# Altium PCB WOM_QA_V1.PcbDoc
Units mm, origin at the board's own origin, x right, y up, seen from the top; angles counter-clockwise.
Board outline 20 x 63 mm, 4 copper layers (Top Layer, Int1 (GND), Int2 (PWR), Bottom Layer), stack 1.426 mm thick; 29 components, 19 nets, 107 pads, 35 vias.
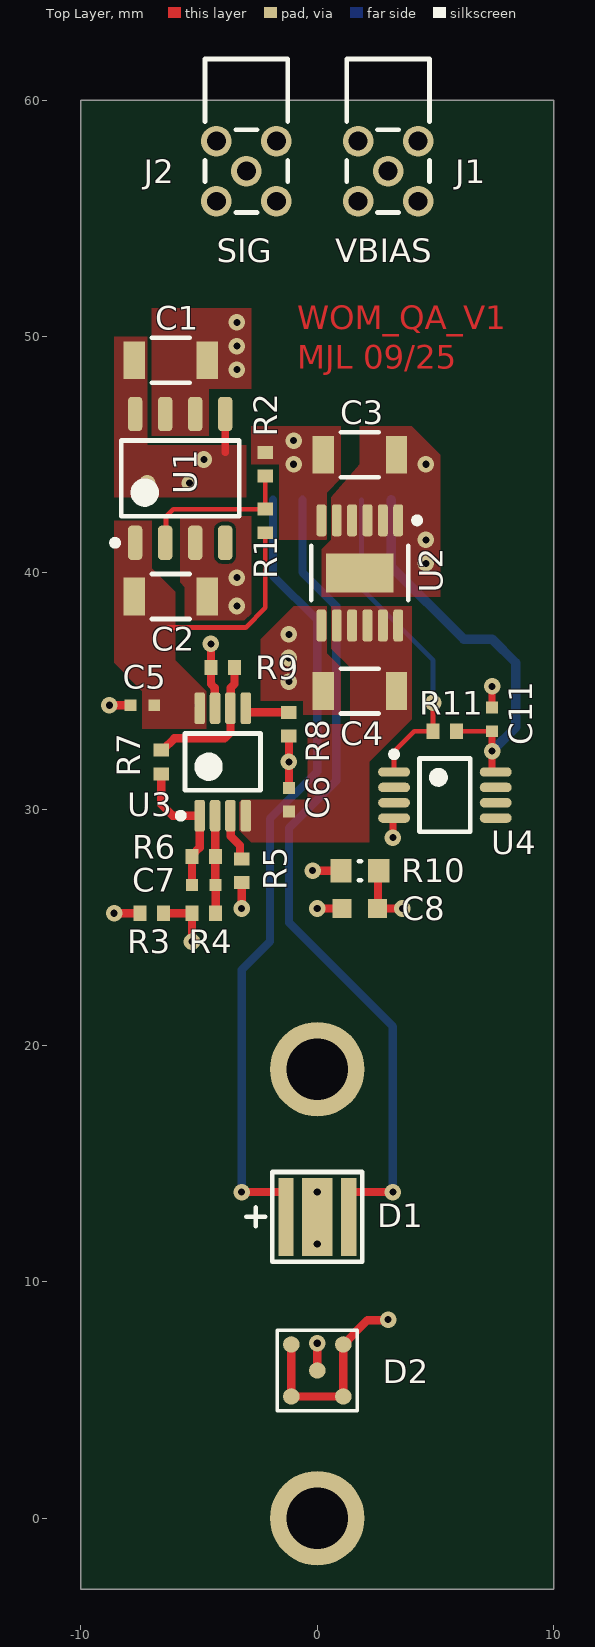
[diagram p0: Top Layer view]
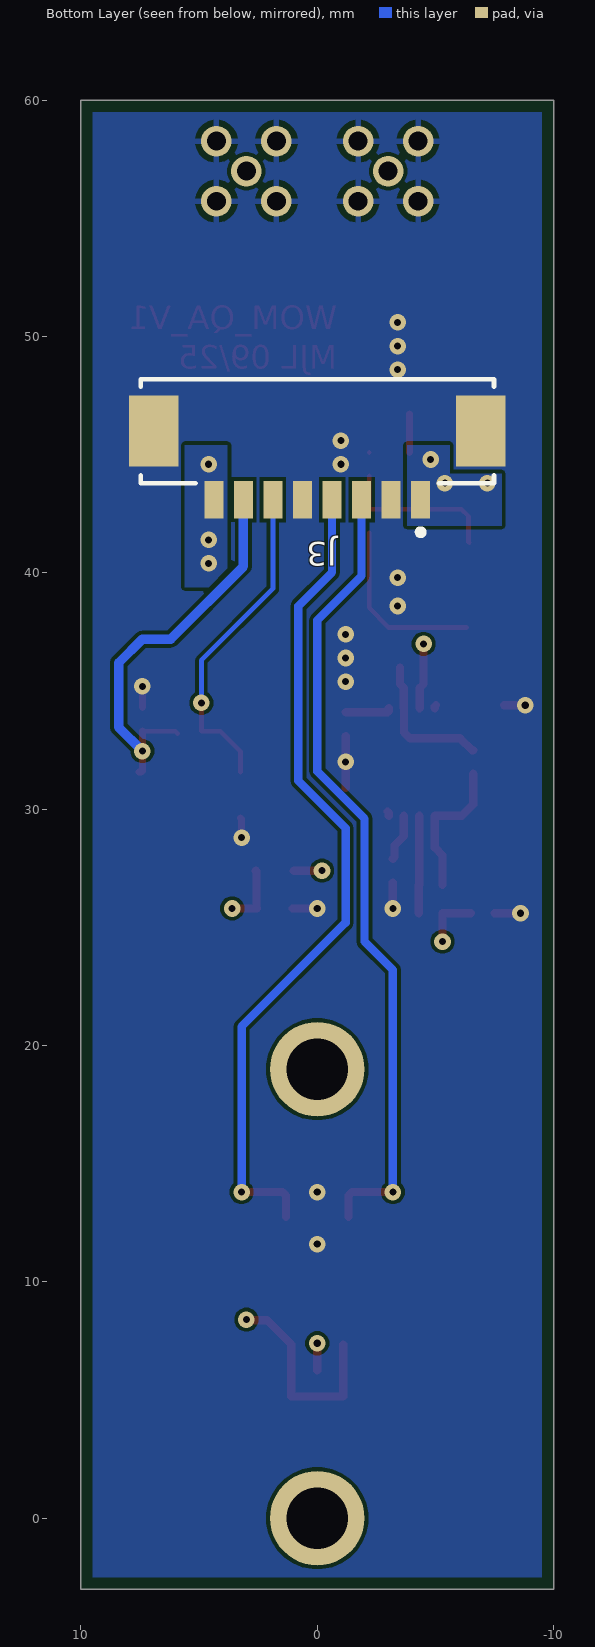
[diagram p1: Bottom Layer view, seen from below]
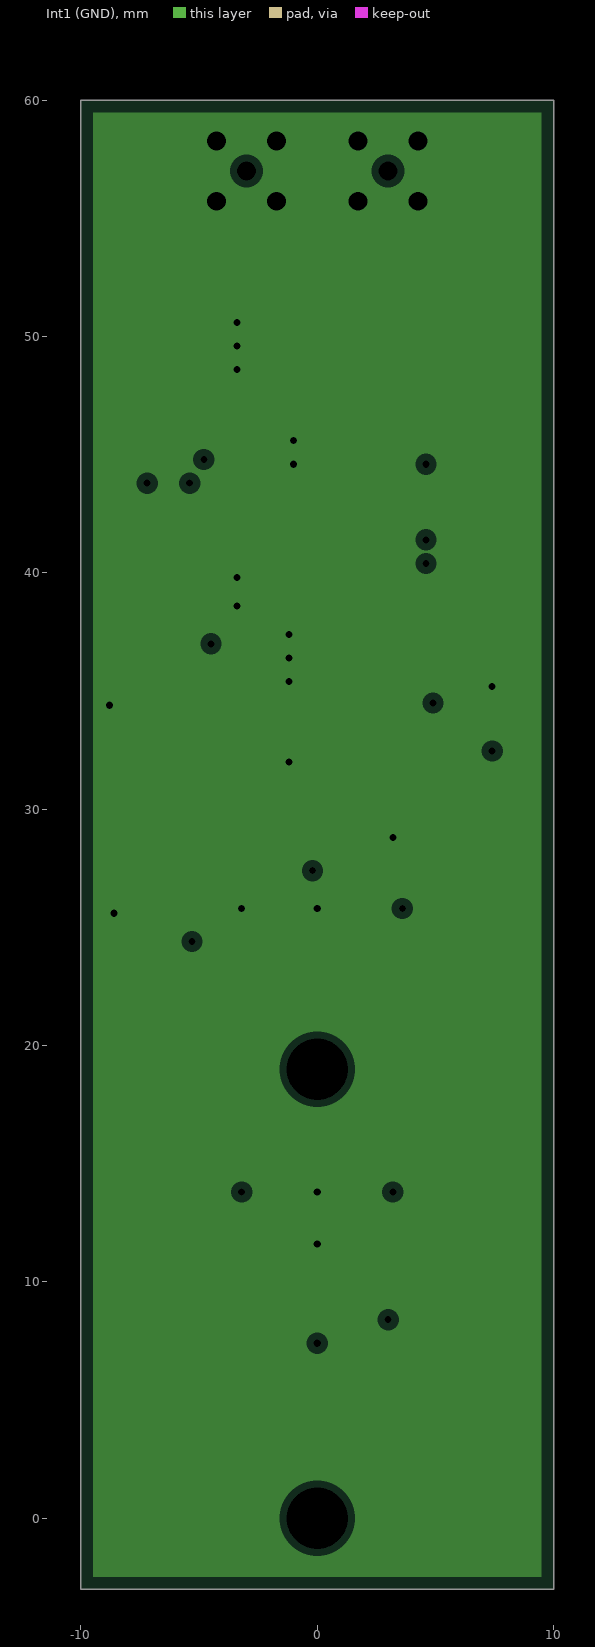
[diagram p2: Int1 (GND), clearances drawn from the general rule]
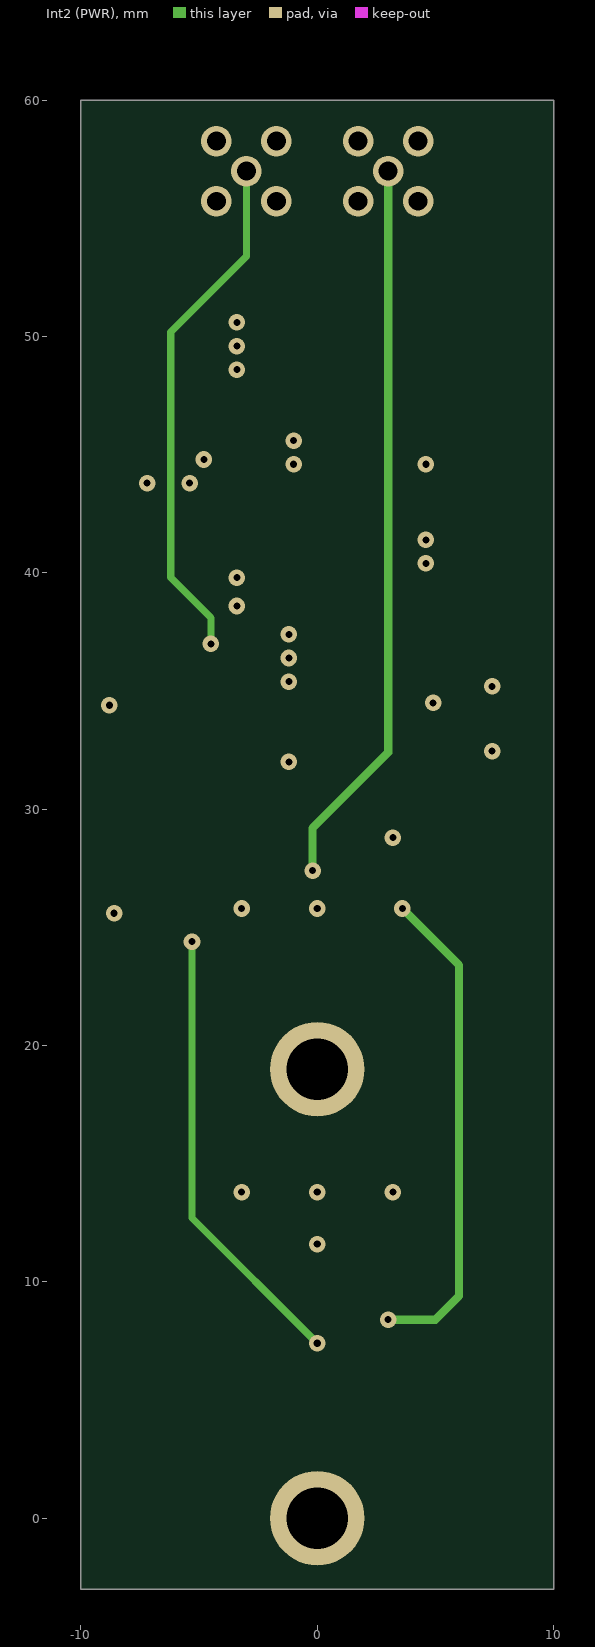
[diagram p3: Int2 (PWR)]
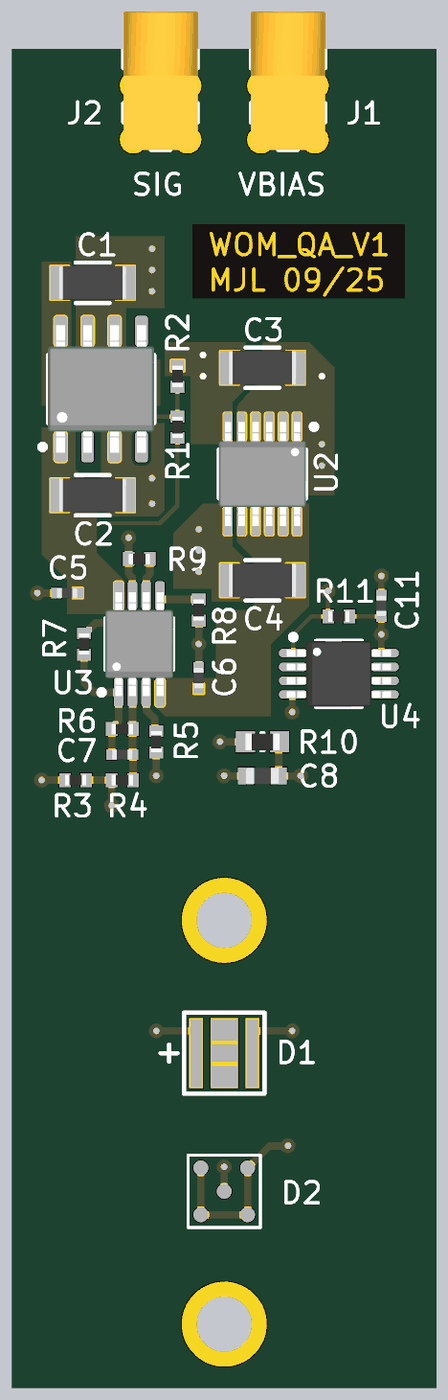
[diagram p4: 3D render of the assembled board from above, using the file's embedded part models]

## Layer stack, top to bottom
Top Solder: solder mask 0.015, SM-001, Dk 3.5
Top Layer: signal copper 0.035
Dielectric 1: prepreg 0.288, PP-017, Dk 4.5
Int1 (GND): plane copper 0.035, net GND
Dielectric 3: core 0.71, Core-039, Dk 4.7
Int2 (PWR): signal copper 0.035
Dielectric 5: prepreg 0.288, PP-017, Dk 4.5
Bottom Layer: signal copper 0.035
Bottom Solder: solder mask 0.015, SM-001, Dk 3.5

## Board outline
-10,-3 10,-3 10,60 -10,60

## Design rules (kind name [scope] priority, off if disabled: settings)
Clearance [All] p1: gap=0.15 ignorepadtopadclearanceinfootprint=FALSE
PlaneClearance [All] p1: clearance=0.3
PlaneConnect [All] p1: pad.planeconnectstyle=Relief pad.reliefexpansion=0.3 pad.reliefentries=4 pad.reliefconductorwidth=0.25 pad.reliefairgap=0.25 via.planeconnectstyle=Direct via.reliefexpansion=0.3 via.reliefentries=4 via.reliefconductorwidth=0.25 via.reliefairgap=0.25
PolygonConnect [All] p1: thpad.connectstyle=Relief thpad.reliefconductorwidth=0.25 thpad.reliefentries=4 thpad.polygonreliefangle="90 Angle" thpad.airgapwidth=0.25 smdpad.connectstyle=Direct smdpad.reliefconductorwidth=0.254 smdpad.reliefentries=4 smdpad.polygonreliefangle="90 Angle" smdpad.airgapwidth=0.254 via.connectstyle=Direct via.reliefconductorwidth=0.254 via.reliefentries=4 via.polygonreliefangle="90 Angle" via.airgapwidth=0.254
RoutingVias [All] p1: holewidth=0.3 width=0.7 viastyle="Through Hole" minholewidth=0.15 minwidth=0.45 maxholewidth=0.711 maxwidth=1.27
SilkToSilkClearance [All] p1: silktosilkclearance=0.15
SolderMaskExpansion SolderMaskExpansion_1 [IsVia] p1: expansion=0.102 istentingtop=TRUE
SolderMaskExpansion [All] p2: expansion=0.05 istentingtop=FALSE
SupplyNets "Schematic Supply Nets_6" [InNet('VDD_TEMP')] p1: voltage=0.000
SupplyNets "Schematic Supply Nets_4" [InNet('-7V0')] p2: voltage=0.000
SupplyNets "Schematic Supply Nets_3" [InNet('-5V0')] p3: voltage=0.000
SupplyNets "Schematic Supply Nets_2" [InNet('GND')] p4: voltage=0.000
SupplyNets "Schematic Supply Nets_1" [InNet('+7V0')] p5: voltage=0.000
SupplyNets "Schematic Supply Nets" [InNet('+5V0')] p6: voltage=0.000
Width Width_S50 [InNetClass('S50')] p1: maxlimit=0.496 minlimit=0.3 preferedwidth=0.496 toplayer_minwidth=0.35 toplayer_maxwidth=0.35 toplayer_prefwidth=0.35 midlayer2_maxwidth=0.3 midlayer2_prefwidth=0.3 bottomlayer_minwidth=0.496 impedanceprofiledriven=TRUE impedanceprofileid={FA672DF7-ECF2-4436-9E1C-940F573E7293} impedanceprofilevalue=50.000000 minimp=50.000000 maximp=50.000000 favimp=50.000000
Width [All] p2: maxlimit=4 minlimit=0.15 preferedwidth=0.25
27 further rules are at their usual default settings.

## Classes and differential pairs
net class S50: NetC7_1 NetC7_2 NetD2_1 NetR7_2 SIG_OUT

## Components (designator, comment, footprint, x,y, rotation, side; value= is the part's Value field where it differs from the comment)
C1 "10uF 16V" WCAP-CSGP_1206_H=1.6mm -6.2,49 r180 top value=10µF
C2 "10uF 16V" WCAP-CSGP_1206_H=1.6mm -6.2,39 r180 top value=10µF
C3 "10uF 16V" WCAP-CSGP_1206_H=1.6mm 1.8,45 r0 top value=10µF
C4 "10uF 16V" WCAP-CSGP_1206_H=1.6mm 1.8,35 r0 top value=10µF
C5 "100nF, 16V" WCAP-CSGP_0402_H=0.5mm -7.4,34.4 r0 top value=100nF
C6 "100nF, 16V" WCAP-CSGP_0402_H=0.5mm -1.2,30.4 r270 top value=100nF
C7 "20 pF 1%, 10V, NP0" WCAP-CSGP_0402_H=0.5mm -4.8,26.8 r180 top value=10pF
C8 "100nF 100V" WCAP-CSGP_0603_H=0.8mm_Reflow 1.8,25.8 r0 top value=100nF
C11 "100nF, 16V" WCAP-CSGP_0402_H=0.5mm 7.4,33.8 r270 top value=100nF
D1 "AUV3-ST32-0SV0K" AUV3-ST32-0SV0K-Footprint-1 0,12.75 r0 top locked
D2 "S13360-3050VE" S13360-3050VE-Footprint-1 0,6.25 r0 top locked
J1 "66011002111501" 66011002111501 3,57 r180 top
J2 "66011002111501" 66011002111501 -3,57 r180 top
J3 "53261-0871" FP-532610871-MFG 0,46 r180 bottom
R1 "3k16 0.1%" RESC0402(1005)_N -2.2,42.2 r270 top
R2 "1k 0.1%" RESC0402(1005)_N -2.2,44.6 r270 top
R3 "DNP" RESC0402(1005)_N -7,25.6 r0 top
R4 "51R 0.5%" RESC0402(1005)_N -4.8,25.6 r180 top
R5 "10R 0.5%" RESC0402(1005)_N -3.2,27.4 r90 top
R6 "2k2 0.5%" RESC0402(1005)_N -4.8,28 r180 top
R7 "510R 0.5%" RESC0402(1005)_N -6.6,32 r90 top
R8 "430R 0.5%" RESC0402(1005)_N -1.2,33.6 r90 top
R9 "2k2 0.5%" RESC0402(1005)_N -4,36 r180 top
R10 "1k 0.5%" RESC0603(1608)_N 1.8,27.4 r180 top
R11 "4k7 1%" RESC0402(1005)_N 5.4,33.3 r0 top
U1 "LT1963AES8#TRPBF" SOIC127P600X175-8N -5.8,44 r90 top
U2 "LT3015EMSE-5#PBF" TSOP65P490X110_HS-13N 1.8,40 r270 top
U3 "ADA4896-2ARMZ" TSOP65P490X110-8N -4,32 r90 top
U4 "DS18B20U+" MAXM-U8+1_V 5.4,30.6 r0 top

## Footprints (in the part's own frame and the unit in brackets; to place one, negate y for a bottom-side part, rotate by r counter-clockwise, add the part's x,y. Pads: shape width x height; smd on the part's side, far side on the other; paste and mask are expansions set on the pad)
66011002111501 [mm] "MMCX PCB THT Jack"
  round 1.3 hole 0.8: 1(0,0) 2(-1.27,1.27) 3(1.27,1.27) 4(1.27,-1.27) 5(-1.27,-1.27)
  silkscreen extent -1.75,-4.75 1.75,1.75, body extent -1.75,-4.75 1.75,1.75, height 3.8
AUV3-ST32-0SV0K-Footprint-1 [mm]
  rect 0.65x3.3 smd paste-0.05 mask+0.05: A(-1.325,0) C(1.325,0)
  rect 1.3x3.3 smd paste-4 mask+0.05: PAD(0,0)
  silkscreen extent -3,-1.9 1.9,1.9, body extent -1.75,-1.75 1.75,1.75, height 3.05
FP-532610871-MFG [mm]
  rect 0.8x1.6 smd paste+0 mask+0: 1(4.375,-2.9) 2(3.125,-2.9) 3(1.875,-2.9) 4(0.625,-2.9) 5(-0.625,-2.9) 6(-1.875,-2.9) 7(-3.125,-2.9) 8(-4.375,-2.9)
  rect 2.1x3 smd paste+0 mask+0: 9(-6.925,0) 10(6.925,0)
  silkscreen extent -7.47,-4.4 7.47,2.2, body extent -7.57,-3.1 7.57,2.1, height 3.6
MAXM-U8+1_V [mm] "SOP, 8-Leads, Body 3.1x3.1mm, Pitch 0.65mm"
  oval 1.35x0.4 smd: 1(-2.15,0.975) 2(-2.15,0.325) 3(-2.15,-0.325) 4(-2.15,-0.975) 5(2.15,-0.975) 6(2.15,-0.325) 7(2.15,0.325) 8(2.15,0.975)
  silkscreen extent -2.27,-1.55 1.07,1.85, body extent -2.45,-1.55 2.45,1.55, height 1.1
RESC0402(1005)_N [mm] "Chip Resistor, Body 1.0x0.5mm, IPC Medium Density"
  rect 0.55x0.65 smd: 1(-0.5,0) 2(0.5,0)
  body extent -0.5,-0.25 0.5,0.25, height 0.3
RESC0603(1608)_N [mm] "Chip Resistor, Body 1.6x0.8mm, IPC Medium Density"
  rect 0.9x1 smd: 1(-0.8,0) 2(0.8,0)
  silkscreen extent -0.05,-0.4 0.05,0.4, body extent -0.8,-0.4 0.8,0.4, height 0.4
S13360-3050VE-Footprint-1 [mm]
  round 0.7 smd mask+0.05: 1(0,0) 2(-1.1,-1.1) 2(-1.1,1.1) 2(1.1,-1.1) 2(1.1,1.1)
  silkscreen extent -1.7,-1.7 1.7,1.7, body extent -1.7,-1.7 1.7,1.7, height 1.4
SOIC127P600X175-8N [mm] "SOIC, 8-Leads, Body 4.90x3.91mm, Pitch 1.27mm, IPC Medium Density"
  rrect50% 1.45x0.6 smd: 1(-2.725,1.905) 2(-2.725,0.635) 3(-2.725,-0.635) 4(-2.725,-1.905) 5(2.725,-1.905) 6(2.725,-0.635) 7(2.725,0.635) 8(2.725,1.905)
  silkscreen extent -2.85,-2.5 1.6,2.88, body extent -3,-2.5 3,2.5, height 1.75
TSOP65P490X110-8N [mm] "TSOP, 8-Leads, Body 3.00x3.00mm, Pitch 0.65mm, IPC Medium Density"
  rrect50% 1.35x0.45 smd mask+0.05: 1(-2.275,0.975) 2(-2.275,0.325) 3(-2.275,-0.325) 4(-2.275,-0.975) 5(2.275,-0.975) 6(2.275,-0.325) 7(2.275,0.325) 8(2.275,0.975)
  silkscreen extent -2.4,-1.6 1.2,1.9, body extent -2.45,-1.6 2.45,1.6, height 1.1
TSOP65P490X110_HS-13N [mm] "TSOP, 12-Leads, Body 4.02x3.00mm, Pitch 0.65mm, Thermal Pad 1.98x1.78mm, IPC Medium Density"
  rrect50% 1.35x0.42 smd mask+0.05: 1(-2.225,1.625) 2(-2.225,0.975) 3(-2.225,0.325) 4(-2.225,-0.325) 5(-2.225,-0.975) 6(-2.225,-1.625) 7(2.225,-1.625) 8(2.225,-0.975) 9(2.225,-0.325) 10(2.225,0.325) 11(2.225,0.975) 12(2.225,1.625)
  rect 1.65x2.85 smd mask+0.05: 13(0,0)
  silkscreen extent -2.35,-2.05 1.15,2.55, body extent -2.45,-2.05 2.45,2.05, height 1.1
WCAP-CSGP_0402_H=0.5mm [mm] "Ceramic Capacitors, body 1x0.5mm"
  rect 0.5x0.5 smd: 1(-0.5,0) 2(0.5,0)
  body extent -0.5,-0.25 0.5,0.25, height 0.5
WCAP-CSGP_0603_H=0.8mm_Reflow [mm] "Ceramic Capacitors, body 1.6x0.8mm"
  rect 0.8x0.8 smd: 1(-0.75,0) 2(0.75,0)
  body extent -0.8,-0.4 0.8,0.4, height 0.8
WCAP-CSGP_1206_H=1.6mm [mm] "Ceramic Capacitors, body 3.2x1.6mm"
  rect 0.9x1.6 smd: 1(-1.55,0) 2(1.55,0)
  silkscreen extent -0.8,-0.95 0.8,0.95, body extent -1.6,-0.8 1.6,0.8, height 1.6

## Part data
C1 C2 C3 C4: library part CMP-010-0785-1, "WCAP-CSGP Multilayer Ceramic Chip Capacitor, General Purpose, size 1206, X7R, 10uF, 16V", Capacitance Tolerance=+/-10%, Isolation Resistance=>{}0.01GOhm, Manufacturer="Wurth Elektronik", Manufacturer Part Number=885012208041, Operating Temperature="-55 to +125degC", Rated Voltage=16VDC
C5 C6 C11: library part CMP-010-0480-1, "WCAP-CSGP Multilayer Ceramic Chip Capacitor, General Purpose, size 0402, X7R, 100nF, 16V", Capacitance Tolerance=+/-10%, Isolation Resistance=>{}5GOhm, Manufacturer="Wurth Elektronik", Manufacturer Part Number=885012205037, Operating Temperature="-55 to +125degC", Rated Voltage=16VDC
C7: library part CMP-010-0006-1, "WCAP-CSGP Multilayer Ceramic Chip Capacitor, General Purpose, size 0402, NP0, 10pF, 10V", Capacitance Tolerance=+/-5%, Isolation Resistance=>{}10GOhm, Manufacturer="Wurth Elektronik", Manufacturer Part Number=885012005007, Operating Temperature="-55 to +125degC", Rated Voltage=10VDC
C8: library part CMP-010-0623-1, "WCAP-CSGP Multilayer Ceramic Chip Capacitor, General Purpose, size 0603, X7R, 100nF, 100V", Capacitance Tolerance=+/-10%, Isolation Resistance=>{}1GOhm, Manufacturer="Wurth Elektronik", Manufacturer Part Number=885012206120, Operating Temperature="-55 to +125degC", Rated Voltage=100VDC
D1: library part CMP-00285-1
D2: library part CMP-00090-1, "MPPC for precision measurement"
J1 J2: library part CMP-002-00434-1, "WR-MMCX PCB Jack, THT, Right Angle, 6GHz, 50O", Frequency Range=6GHz, Manufacturer="Wurth Elektronik", Operating Temperature Max=155°C, Operating Temperature Min=-55°C
J3: library part CMP-002-00452-2, "1.25mm (.049\") Pitch PicoBlade Header, Surface Mount, Right Angle, Lead-free, 8 Circuits", Max Operating Temperature=105°C, Min Operating Temperature=-40°C
R1: library part CMP-015-0047-1, "Res Thin Film 0402 3.16K Ohm 0.1% 1/16W ±25ppm/°C Molded SMD Punched Carrier T/R", Case Code (Imperial)=0402, Case Code (Metric)=1005, Max Operating Temperature=155°C, Max Power Dissipation=63mW, Min Operating Temperature=-55°C, Package Quantity=1, Resistance=3.16kR, Resistor Type="Thin Film", Temperature Coefficient=25ppm/°C, Tolerance=0.1%, Voltage Rating=25V, Voltage Rating (DC)=50V
R2: library part CMP-009-00196-1, Case Code (Imperial)=0402, Case Code (Metric)=1005, Max Operating Temperature=155°C, Max Power Dissipation=63mW, Min Operating Temperature=-55°C, Package Quantity=1, Resistance=1kR, Temperature Coefficient=25ppm/°C, Tolerance=0.1%, Voltage Rating=25V, Voltage Rating (DC)=50V
R3 R4: library part CMP-009-00205-1, Case Code (Imperial)=0402, Case Code (Metric)=1005, Max Operating Temperature=155°C, Max Power Dissipation=63mW, Min Operating Temperature=-55°C, Package Quantity=1, Power Rating=62.5mW, Resistance=51R, Temperature Coefficient=25ppm/°C, Tolerance=0.5%
R5: library part CMP-015-0063-1, "Res, 10R, 0.5%, 0.1W, 0402 Rohs Compliant: Yes", Case Code (Imperial)=0402, Case Code (Metric)=1005, Max Operating Temperature=155°C, Max Power Dissipation=100mW, Min Operating Temperature=-55°C, Package Quantity=10000, Resistance=10R, Resistance Tolerance=5%, Resistor Type="Thick Film", Temperature Coefficient=200ppm/°C, Voltage Rating=50V
R6 R9: library part CMP-015-0062-1, "Res, 2K2, 0.5%, 0.1W, 0402 Rohs Compliant: Yes", Case Code (Imperial)=0402, Case Code (Metric)=1005, Max Operating Temperature=155°C, Max Power Dissipation=100mW, Min Operating Temperature=-55°C, Package Quantity=10000, Resistance=2kR, Resistance Tolerance=1%, Resistor Type="Thick Film", Temperature Coefficient=100ppm/°C, Voltage Rating=50V
R7: library part CMP-015-0064-1, Case Code (Imperial)=0402, Case Code (Metric)=1005, Max Operating Temperature=155°C, Max Power Dissipation=100mW, Min Operating Temperature=-55°C, Package Quantity=1, Resistance=523R, Resistance Tolerance=1%, Resistor Type="Thick Film", Temperature Coefficient=100ppm/°C, Voltage Rating=50V
R8: library part CMP-015-0065-1, "Res Thick Film 0402 430 Ohm 0.5% 0.063W(1/16W) ±50ppm/C Pad SMD Automotive T/R", Case Code (Imperial)=0402, Case Code (Metric)=1005, Max Operating Temperature=125°C, Max Power Dissipation=100mW, Min Operating Temperature=-55°C, Package Quantity=1, Power Rating=63mW, Resistance=430R, Resistor Type="Thick Film", Temperature Coefficient=50ppm/°C, Tolerance=0.5%, Voltage Rating=50V
R10: library part CMP-015-0043-1, "Res Thick Film 0603 1K Ohm 0.5% 0.063W ±50ppm/°C Molded SMD Punched Carrier T/R", Case Code (Imperial)=0603, Case Code (Metric)=1608, Max Operating Temperature=125°C, Min Operating Temperature=-55°C, Package Quantity=5000, Power Rating=100mW, Resistance=1kR, Resistor Type="Thick Film", Temperature Coefficient=50ppm/°C, Tolerance=0.5%, Voltage Rating=75V
R11: library part CMP-009-00213-1, Case Code (Imperial)=0402, Case Code (Metric)=1005, Max Operating Temperature=155°C, Max Power Dissipation=100mW, Min Operating Temperature=-55°C, Package Quantity=1, Resistance=4.7kR, Resistor Type="Thick Film", Temperature Coefficient=100ppm/°C, Tolerance=1%, Voltage Rating=50V
U1: library part CMP-00189-1, "IC REG LDO ADJ 1.5A 8SOIC"
U2: library part CMP-00188-1, "LT3015 - 1.5A, Low Noise, Negative Linear Regulator with Precision Current Limit"
U3: library part CMP-00187-1, "Op Amp Dual Low Power Amplifier R-R O/P ±5V/10V 8-Pin MSOP Tube"
U4: library part CMP-019-00016-2, "Programmable Resolution 1-Wire Digital Thermometer, -55 to 125 degC, 8-Pin SOP, RoHS, Tube", Case/Package=MSOP, Manufacturer=Maxim, Max Operating Temperature=125°C, Max Supply Voltage=5.5V, Max Supply Voltage (DC)=5V, Min Operating Temperature=-55°C, Min Supply Voltage=3V, Nominal Supply Current=1mA, Output Current=4mA, Package Description="8-Pin Small Outline Package Integrated Circuit, Body 3 x 3 mm, Pitch 0.65 mm", Package Quantity=50, Package Reference=U8+1

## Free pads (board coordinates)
  round 4 hole 2.6 mask+0.05: MH(0,0) MH1(0,19)

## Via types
v1: diameter 0.7, hole 0.3, Top Layer to Bottom Layer, tented both sides, 35 vias

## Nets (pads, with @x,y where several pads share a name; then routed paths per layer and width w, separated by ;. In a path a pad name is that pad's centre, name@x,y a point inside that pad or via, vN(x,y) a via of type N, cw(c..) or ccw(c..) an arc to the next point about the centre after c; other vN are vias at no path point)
1-WIRE: J3.6 R11.1 U4.1 | length 13.9
  Top Layer w0.2: U4.1 3.25,32.45 4.1,33.3 R11.1 v1(4.9,34.5)
  Bottom Layer w0.2: J3.6 1.875,39.325 4.9,36.3 v1(4.9,34.5)
+5V0: C2.2 C5.2 R1.2 U1.1 U3.8 | length 7.8
  Top Layer w0.2: -6.312,37.688 -3.034,37.688 -2.2,38.521 R1.2
  Top Layer w0.35: U3.8@-5.025,34.4 -4.975,34.35 U3.8
+7V0: C1.2 J3.1 U1.5 U1.8 | length 1.6
  Top Layer w0.3: -3.895,45.105 U1.5
  other v1: -7.2,43.8 -5.4,43.8 -4.8,44.8
-5V0: C4.2 C6.2 U2.8 U2.9 U2.10 U2.11 U2.12 U3.4 | length 0.2
  Top Layer w0.35: U3.4 -3.025,29.85 U3.4@-2.975,29.9
-7V0: C3.2 J3.8 U2.1 U2.2 U2.3 U2.4 U2.5 U2.13
  other v1: 4.6,40.4 4.6,41.4 4.6,44.6
GND: C1.1 C2.1 C3.1 C4.1 C5.1 C6.1 C8.1 C11.1 D1.PAD J1.2 J1.3 J1.4 J1.5 J2.2 J2.3 J2.4 J2.5 J3.2 J3.5 J3.9 J3.10 R2.1 R3.1 R5.1 R8.1 U1.3 U1.6 U1.7 U2.6 U2.7 U4.4 | length 8.1
  Top Layer w0.3: v1(3.2,28.8) 3.2,29.579 3.246,29.625 U4.4 ; C11.1 v1(7.4,35.2)
  Top Layer w0.35: v1(-8.8,34.4) C5.1 ; v1(-8.6,25.6) R3.1 ; v1(-3.2,25.8) R5.1 ; C6.1 R8.1 ; v1(0,25.8) C8.1
  other v1: 0,11.6 0,13.8 -1.2,32 -1.2,35.4 -1.2,36.4 -1.2,37.4 -3.4,38.6 -3.4,39.8 -1,44.6 -1,45.6 -3.4,48.6 -3.4,49.6 -3.4,50.6
NetC7_1: C7.1 R4.1 R6.1 U3.2 | length 4.1
  Top Layer w0.35: U3.2 -4.313,29.713 -4.313,26.812 C7.1 R4.1
NetC7_2: C7.2 R6.2 R7.1 U3.1 | length 6.1
  Top Layer w0.35: R7.1 -6.6,30.2 -6.125,29.725 U3.1 -4.975,28.375 R6.2@-5.3,28.05 ; C7.2 R6.2
NetC8_2: C8.2 D2.2 R10.1 | length 32.4
  Top Layer w0.35: D2.2@-1.1,7.35 -1.1,5.15 1.1,5.15 1.1,7.35 2.125,8.375 2.975,8.375 v1(3,8.4) ; R10.1 2.575,27.375 2.575,25.825 C8.2 v1(3.6,25.8)
  Int2 (PWR) w0.35: v1(3,8.4) 5,8.4 6,9.4 6,23.4 v1(3.6,25.8)
NetD2_1: D2.1 R3.2 R4.2 | length 22.7
  Top Layer w0.35: R3.2 R4.2 v1(-5.3,24.4) ; D2.1 v1(0,7.4)
  Int2 (PWR) w0.3: v1(-5.3,24.4) -5.3,12.7 v1(0,7.4)
NetR1_1: R1.1 R2.2 U1.2 | length 6.9
  Top Layer w0.2: U1.2 -6.4,41.31 -6.4,42.4 -6.1,42.7 R1.1 R2.2
NetR5_2: R5.2 U3.3 | length 2
  Top Layer w0.35: U3.3 -3.662,29.712 -3.662,28.862 -3.271,28.471 -3.271,27.971 R5.2
NetR7_2: R7.2 R9.1 U3.6 | length 6.1
  Top Layer w0.35: R7.2 -6.55,32.5 -6.05,33 -3.923,33 -3.675,33.248 U3.6 -3.662,34.288 -3.662,35.138 -3.5,35.3 R9.1
NetR8_2: R8.2 U3.5 | length 2
  Top Layer w0.35: U3.5 -3.025,34.15 -2.975,34.1 R8.2
RTN_LED: D1.C J3.4 | length 35.4
  Top Layer w0.35: D1.C 1.325,13.65 1.475,13.8 v1(3.2,13.8)
  Bottom Layer w0.35: J3.4 -0.625,40.025 0.8,38.6 0.8,31.2 -1.2,29.2 -1.2,25.2 3.2,20.8 v1(3.2,13.8)
SIG_OUT: J2.1 R9.2 U3.7 | length 24.8
  Top Layer w0.35: v1(-4.5,37) R9.2 -4.5,35.3 -4.338,35.138 -4.338,34.288 U3.7
  Int2 (PWR) w0.3: v1(-4.5,37) -4.5,38.1 -6.2,39.8 -6.2,50.2 -3,53.4 J2.1
VBIAS: J1.1 R10.2 | length 32.1
  Top Layer w0.35: v1(-0.2,27.4) R10.2
  Int2 (PWR) w0.35: v1(-0.2,27.4) -0.2,29.2 3,32.4 J1.1
VDD_LED: D1.A J3.3 | length 34.2
  Top Layer w0.35: v1(-3.2,13.8) -1.475,13.8 -1.325,13.65 D1.A
  Bottom Layer w0.35: v1(-3.2,13.8) -3.2,23.2 -2,24.4 -2,29.6 0,31.6 0,38 -1.875,39.875 J3.3
VDD_TEMP: C11.2 J3.7 R11.2 U4.8 | length 17.3
  Top Layer w0.2: R11.2@5.9,33.2 6,33.3 C11.2
  Top Layer w0.3: C11.2 v1(7.4,32.461) 7.4,31.621 7.446,31.575 U4.8
  Bottom Layer w0.4: J3.7 3.125,40.275 6.2,37.2 7.4,37.2 8.4,36.2 8.4,33.46 v1(7.4,32.461)
pads on no net: U1.4 U4.2 U4.3 U4.5 U4.6 U4.7

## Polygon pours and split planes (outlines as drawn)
GND on Top Layer "GND_L01_P008" (solid, pour order 8): -7,45.8 -4.6,45.8 -4.6,47.8 -2.8,47.8 -2.8,51.2 -7,51.2
-7V0 on Top Layer "-7V0_L01_P006" (solid, pour order 6): 4,46.2 5.2,45 5.2,39 0.2,39 0.2,41 0.6,41.4 0.6,43.2 1.8,44.6 1.8,46.2
GND on Top Layer "GND_L01_P010" (solid, pour order 10): 0.4,41.4 0.4,43.4 1,44 1,46.2 -2.8,46.2 -2.8,44.6 -1.6,44.6 -1.6,41.4
-5V0 on Top Layer "-5V0_L01_P009" (solid, pour order 9): 0.6,38.6 0.6,36.8 1.4,36 1.4,33.6 -0.4,33.6 -0.4,30.4 -3.4,30.4 -3.4,29.2 -2.8,28.6 2.2,28.6 2.2,32 4,33.8 4,38.6
+7V0 on Top Layer "+7V0_L01_P004" (solid, pour order 4): -7.2,50 -7.2,45.4 -3,45.4 -3,43.2 -8.6,43.2 -8.6,50
GND on Top Layer "GND_L01_P003" (solid, pour order 3): -0.6,34 -0.6,34.6 -2.4,34.6 -2.4,37.2 -1,38.6 0.4,38.6 0.4,36.6 1,36 1,34
GND on Top Layer "GND_L01_P001" (solid, pour order 1): -5.8,42.4 -5.8,39.6 -5.6,39.4 -5.6,38 -2.8,38 -2.8,42.4
+5V0 on Top Layer "+5V0_L01_P000" (solid, pour order 0): -7,42.2 -7,40.2 -6,39.2 -6,36.3 -4.7,35 -4.7,33.4 -7.4,33.4 -7.4,35 -8.6,36.2 -8.6,42.2
+7V0 on Bottom Layer "+7V0_L04_P017" (solid, pour order 17): -5.6,44.2 -7.8,44.2 -7.8,42 -3.8,42 -3.8,45.4 -5.6,45.4
-7V0 on Bottom Layer "-7V0_L04_P016" (solid, pour order 16): 3.8,40.2 4.6,39.4 5.6,39.4 5.6,45.4 3.8,45.4
GND on Bottom Layer "GND_L04_P015" (solid, pour order 15): -9.5,59.5 9.5,59.5 9.5,-2.5 -9.5,-2.5
GND on Int1 (GND) (split plane): 9.49,-2.49 -9.49,-2.49 -9.49,59.49 9.49,59.49

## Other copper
Top Layer:
  text "WOM_QA_V1" at -0.85,50.317 h1
  text "MJL 09/25" at -0.85,48.65 h1

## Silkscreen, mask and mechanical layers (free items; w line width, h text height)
Top Overlay:
  text "SIG" at -4.25,53.15 h1
  text "VBIAS" at 0.751,53.15 h1
Top Solder:
  rectangle: -1.5,48.25 8.5,51.75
